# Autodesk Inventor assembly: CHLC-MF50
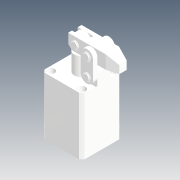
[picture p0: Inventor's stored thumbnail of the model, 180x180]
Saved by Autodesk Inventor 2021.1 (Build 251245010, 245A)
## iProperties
Company: Microsoft
Created: 2019-11
Part Number: CHLC-MF50
Description: STEP AP214
Document SubType Name: Assembly
Designer: user
Title: chlc-mf50_asm.STEP
Author: Windows
Revision Number: ÈÎºÎ
Sending System: SolidWorks 2015
Preprocessor: SwSTEP 2.0
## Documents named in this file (13)
- D:\Vault_2016\Projekty\Clamptek\Hydraulic\CHLC\CHLC-50\Inventor\CHLC-MF50\CHLC-MF50.iam
- D:\Vault_2016\Projekty\Clamptek\Hydraulic\CHLC\CHLC-50\Inventor\CHLC-MF50\CHLC-MF50-01.ipt
- D:\Vault_2016\Projekty\Clamptek\Hydraulic\CHLC\CHLC-50\Inventor\CHLC-MF50\CHLC-MF50-02.ipt
- D:\Vault_2016\Projekty\Clamptek\Hydraulic\CHLC\CHLC-50\Inventor\CHLC-MF50\CHLC-50-09.ipt
- D:\Vault_2016\Projekty\Clamptek\Hydraulic\CHLC\CHLC-50\Inventor\CHLC-MF50\CHLC-50-01.ipt
- D:\Vault_2016\Projekty\Clamptek\Hydraulic\CHLC\CHLC-50\Inventor\CHLC-MF50\CHLC-50-03.ipt
- D:\Vault_2016\Projekty\Clamptek\Hydraulic\CHLC\CHLC-50\Inventor\CHLC-MF50\CHLC-50-02.ipt
- D:\Vault_2016\Projekty\Clamptek\Hydraulic\CHLC\CHLC-50\Inventor\CHLC-MF50\CHLC-50-04.ipt
- D:\Vault_2016\Projekty\Clamptek\Hydraulic\CHLC\CHLC-50\Inventor\CHLC-MF50\TXF_ASM.iam
- D:\Vault_2016\Projekty\Clamptek\Hydraulic\CHLC\CHLC-50\Inventor\CHLC-MF50\M6.ipt
- D:\Vault_2016\Projekty\Clamptek\Hydraulic\CHLC\CHLC-50\Inventor\CHLC-MF50\CHLC-50-06.ipt
- D:\Vault_2016\Projekty\Clamptek\Hydraulic\CHLC\CHLC-50\Inventor\CHLC-MF50\M6LS.ipt
- D:\Vault_2016\Projekty\Clamptek\Hydraulic\CHLC\CHLC-50\Inventor\CHLC-MF50\M6LC.ipt
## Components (20 placed, 20 different names)
1. CHLC-MF50-01_1
2. CHLC-MF50-02_2
3. CHLC-50-09_3
4. CHLC-50-01_4
5. CHLC-50-03_5
6. CHLC-50-03_6
7. CHLC-50-02_7
8. CHLC-50-04_8
9. CHLC-50-04_9
10. TXF_ASM_10 [sub-assembly]
11. M6_11
12. CHLC-50-06_12
13. CHLC-50-06_13
14. CHLC-50-06_14
15. CHLC-50-06_15
16. CHLC-50-06_16
17. CHLC-50-06_17
18. M6LS_18
19. M6LC_19
20. M6LC_20
